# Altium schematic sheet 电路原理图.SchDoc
size 419 x 297 mm
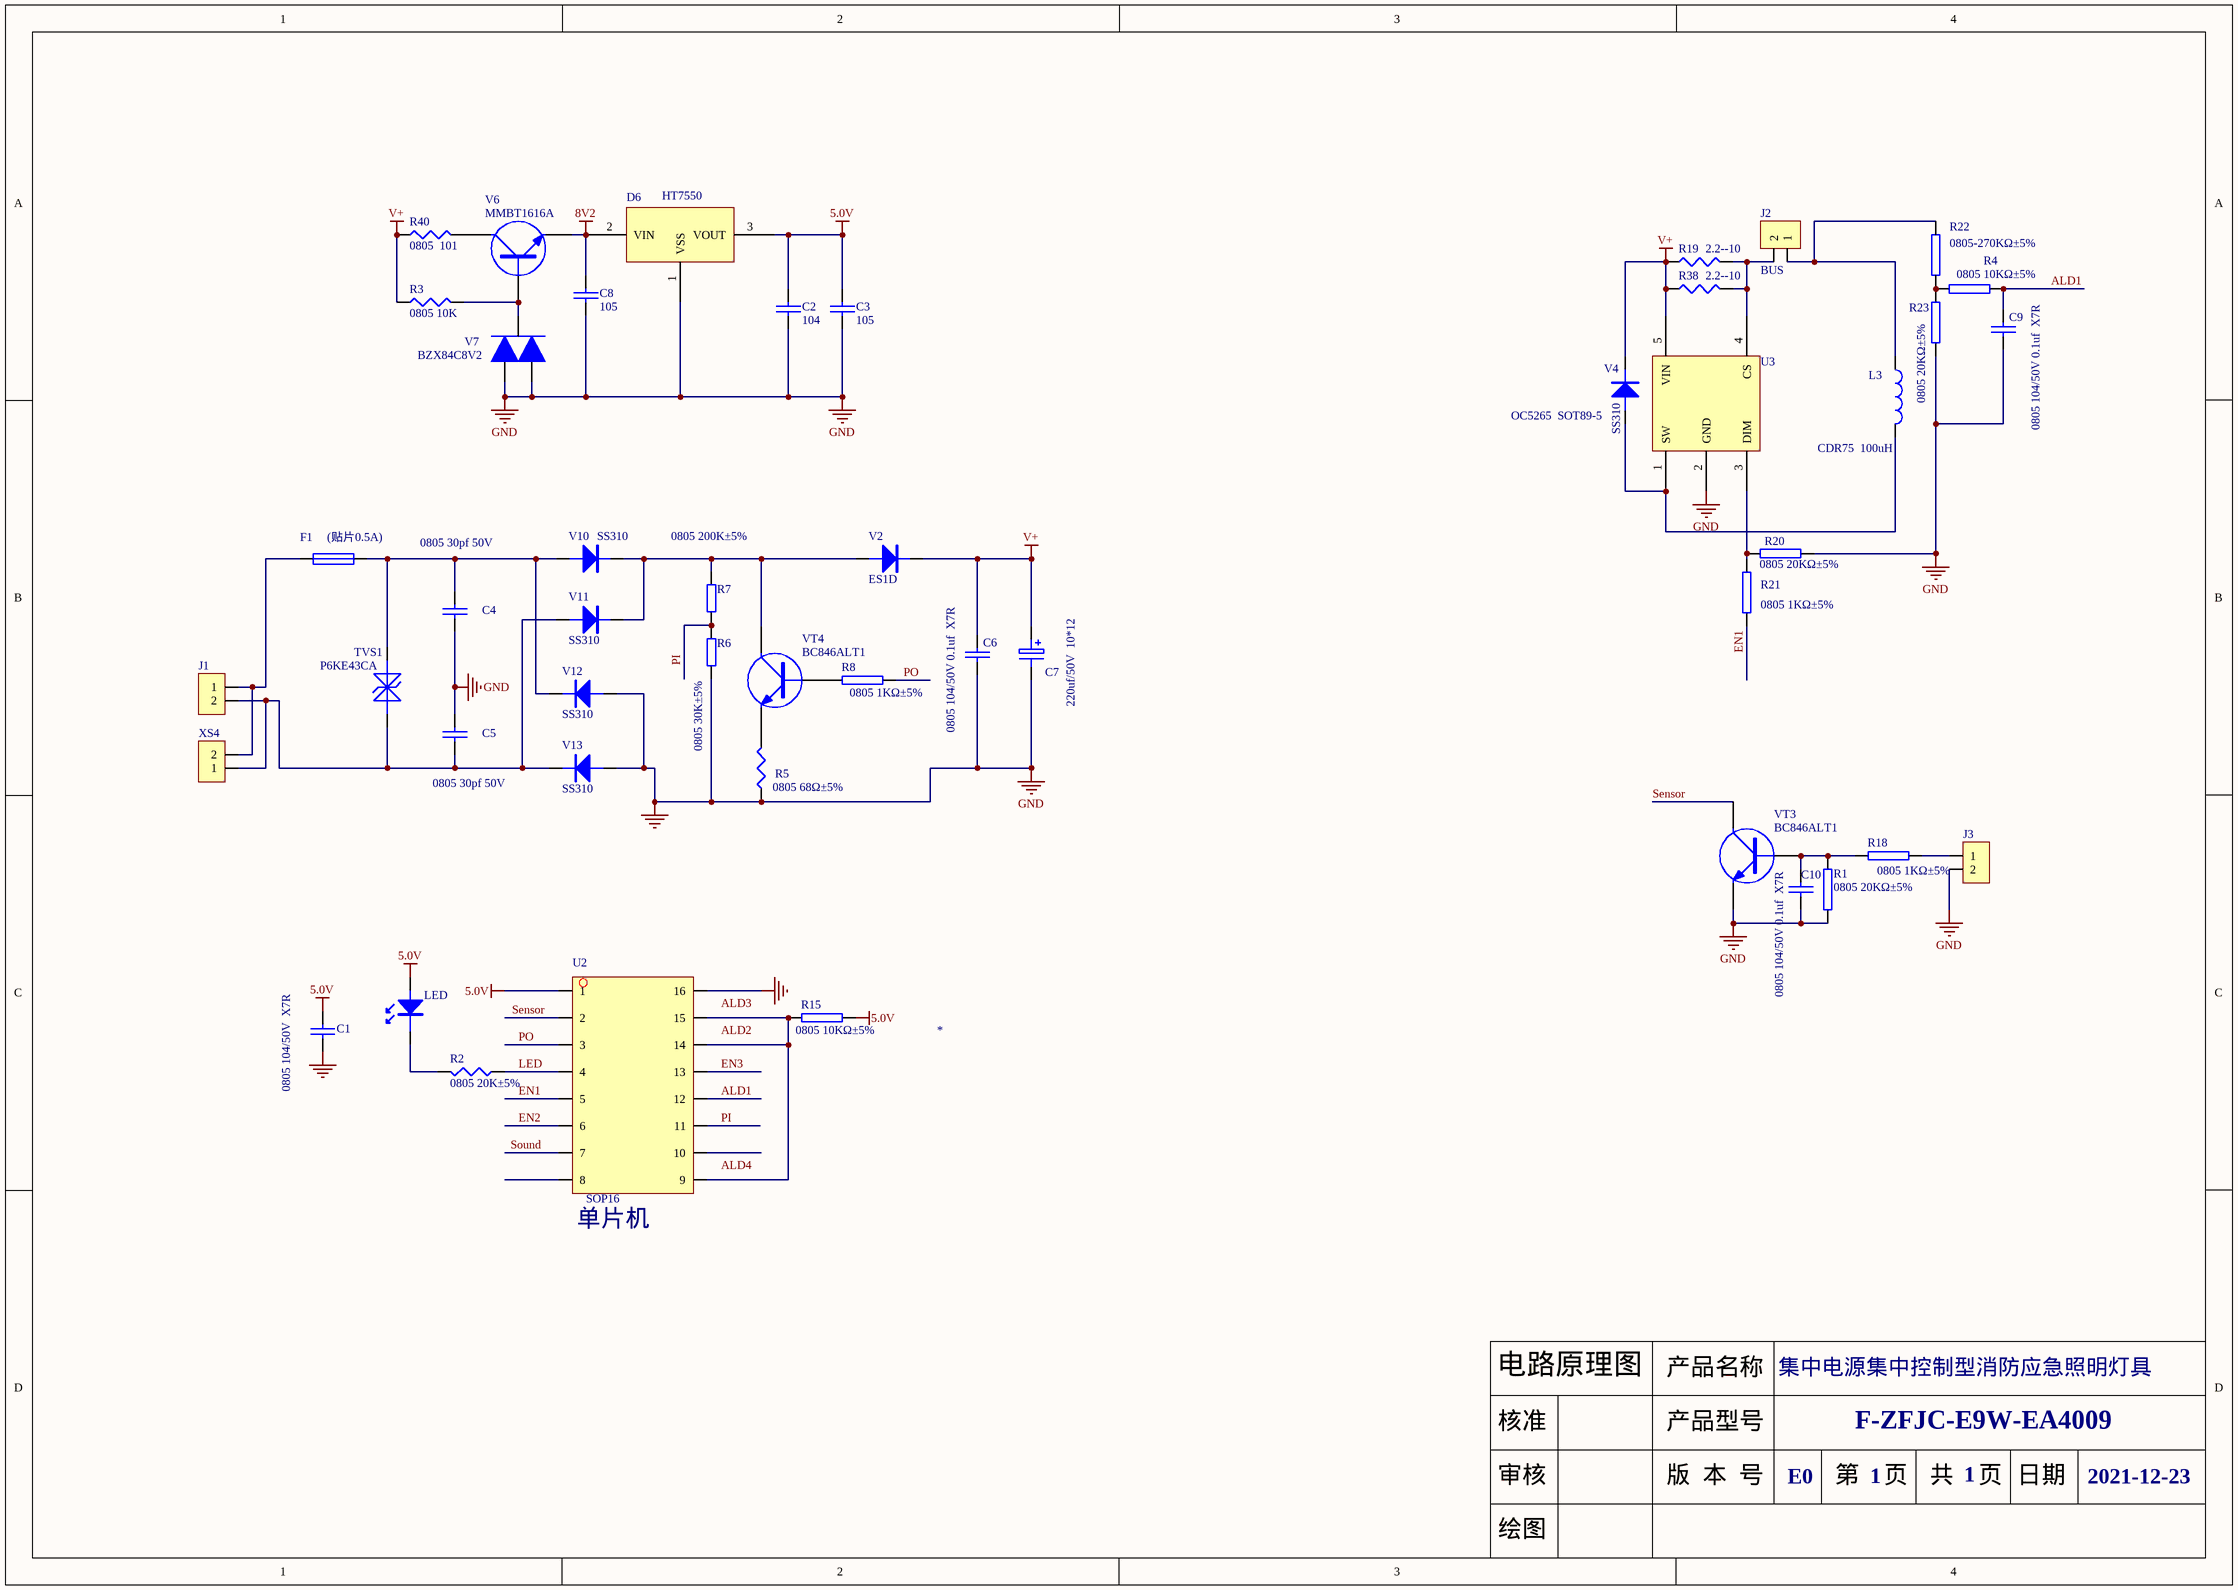
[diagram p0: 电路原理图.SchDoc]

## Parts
C1  0805 104/50V  X7R  [0805-C]
C2  104  [0805-c]
C3  105  [0805-C]
C4  0805 30pf 50V  [0805-c]
C5  0805 30pf 50V  [0805-c]
C6  0805 104/50V 0.1uf  X7R  [0805-c]
C7  220uf/50V  10*12  [CE10]
C8  105  [0805-C]
C9  0805 104/50V 0.1uf  X7R  [0805-c]
C10  0805 104/50V 0.1uf  X7R  [0805-c]
D6  HT7550  [SOT-89]
F1  (贴片0.5A)  [贴片保险]
J1  BUS  [SMT_J2]  (value not drawn)
J2  BUS  [贴片座子PCB封装]
J3  (no value)  [贴片座子PCB封装]
L3  CDR75  100uH  [L8]
LED  (no value)  [LED0805]
R1  0805 20KΩ±5%  [0805]
R2  0805 20K±5%  [0805]
R3  0805 10K  [1206]
R4  0805 10KΩ±5%  [0805]
R5  0805 68Ω±5%  [0805]
R6  0805 30K±5%  [0805]
R7  0805 200K±5%  [0805]
R8  0805 1KΩ±5%  [0805]
R15  0805 10KΩ±5%  [0805]
R18  0805 1KΩ±5%  [0805]
R19  2.2--10  [1206]
R20  0805 20KΩ±5%  [0805]
R21  0805 1KΩ±5%  [0805]
R22  0805-270KΩ±5%  [0805]
R23  0805 20KΩ±5%  [0805]
R38  2.2--10  [1206]
R40  0805  101  [0805]
TVS1  P6KE43CA  [SMT_TVS]
U2  SOP16  [SOP-16b]
U3  OC5265  SOT89-5  [SOT-89-5]
V2  ES1D  [SMA]
V4  SS310  [SMA]
V6  MMBT1616A  [SOT-23]
V7  BZX84C8V2  [SOT-23]
V10  SS310  [SMA]
V11  SS310  [SMA]
V12  SS310  [SMA]
V13  SS310  [SMA]
VT3  BC846ALT1  [SOT-23]
VT4  BC846ALT1  [SOT-23]
XS4  BUS  [TJC-2]  (value not drawn)

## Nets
5.0V: C1.2 C2.2 C3.2 D6.3(VOUT) LED.A R15.1 U2.1
8V2: C8.2 D6.2(VIN) V6.2(E)
GND: C1.1 C2.1 C3.1 C4.2 C5.1 C6.2 C7.2 C8.1 C9.2 C10.2 D6.1(VSS) J3.2 R1.2 R5.1 R6.1 R20.1 R23.1 U2.16 U3.2(GND) V7.1 V7.2 V12.A V13.A VT3.2(E)
V+: C6.1 C7.1 R3.1 R19.1 R38.1 R40.1 U3.5(VIN) V2.K V4.K
ALD1: C9.1 R4.1 U2.12
EN1: R21.1 U2.5
EN2: U2.6
EN3: U2.13
LED: R2.1 U2.4
PI: R6.2 R7.1 U2.11
PO: R8.2 U2.3
Sensor: U2.2 VT3.3(C)
Sound: U2.7
NetC4_1: C4.1 F1.2 TVS1.A V10.A V12.K
NetC5_2: C5.2 J1.2 TVS1.K V11.A V13.K XS4.1
NetC10_1: C10.1 R1.1 R18.1 VT3.1(B)
NetF1_1: F1.1 J1.1 XS4.2
NetJ2_1: J2.1 L3.1 R22.2
NetJ2_2: J2.2 R19.2 R38.2 U3.4(CS)
NetJ3_1: J3.1 R18.2
NetL3_2: L3.2 U3.1(SW) V4.A
NetLED_K: LED.K R2.2
NetR3_2: R3.2 V6.1(B) V7.3
NetR4_2: R4.2 R22.1 R23.2
NetR5_2: R5.2 VT4.2(E)
NetR7_2: R7.2 V2.A V10.K V11.K VT4.3(C)
NetR8_1: R8.1 VT4.1(B)
NetR15_2: R15.2 U2.9 U2.14 U2.15
NetR20_2: R20.2 R21.2 U3.3(DIM)
NetR40_2: R40.2 V6.3(C)

Not connected (* = marked no-connect by the designer): U2 8 10

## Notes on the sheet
- (near U2) 单片机
- 集中电源集中控制型消防应急照明灯具
- F-ZFJC-E9W-EA4009
- E0
- 1
- 2021-12-23
- Labels drawn without touching a wire or pin: ALD2, ALD3, ALD4

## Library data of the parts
C1 = CAP: 料号: 4.1.CTX.004; 型号规格: 104/50V ±10% X7R; 名称: 0603封装贴片电容
C2 C3 C8 = CAP
C4 C5 = CAP: 料号: 4.1.CTX.054; 型号规格: 30PF/50V ±10% X7R 5000H RoHS; 名称: 0603封装贴片电容
C6 C9 C10 = CAP: 料号: 4.1.CTX.004; 型号规格: 104/50V ±10% X7R 5000H RoHS; 名称: 0603封装贴片电容
C7 = ELECTRO1: 料号: 4.1.C.113; 型号规格: 330UF/50V 10*16 105℃ 误差±20% 5000-10000H 脚长(3.2-3.5mm); 名称: 电解电容
D6 = LDO
F1 = FUSE1: 料号: 4.3.X.111; 型号规格: 仓 24F系列 快断保险管 2A250V; 名称: 贴片保险管
J1 = CON2: 新料: 无
J2 = CON2: 型号规格: XH2.5-2A 白色直插针; 名称: 直插针座
J3 = CON2: 料号: 无; 型号规格: XH2.5-2A 白色直插针; 名称: 直插针座
L3 = INDUCTOR: 料号: 4.5.LG.151; 型号规格: CD54-100uH; 名称: 贴片电感
LED = LED: 料号: 4.3.LED.250; 名称: 发光二极管; 型号规格: C0805UG-ES 高亮白发绿贴片 VF:2.8-3.0 IV:250-300 WLD:515-520  IF:30MA
R1 R20 = RES2: 料号: 4.2.RTX.003; 型号规格: 103(10KΩ) ±5%; 名称: 0603封装贴片电阻
R2 = RES1: 料号: 4.2.RTD.246; 型号规格: 15R(15Ω) ±1%RoHS; 名称: 0805封装贴片电阻
R3 R40 = RES1
R4 R23 = RES2: 料号: 4.2.RTX.035A; 型号规格: 203(20KΩ) ±1%; 名称: 0603封装贴片电阻
R5 = RES1: 料号: 4.2.RTD.244; 型号规格: 680(68Ω) ±5%; 名称: 0805封装贴片电阻
R6 = RES: 料号: 4.2.RTD.044; 型号规格: 203(20KΩ) ±5%; 名称: 0805封装贴片电阻
R7 = RES: 料号: 4.2.RTD.130; 型号规格: 274(270KΩ) ±5%; 名称: 0805封装贴片电阻
R8 R15 R21 = RES2: 料号: 4.2.RTX.002; 型号规格: 102(1KΩ) ±5%; 名称: 0603封装贴片电阻
R18 = RES2: 料号: 无; 名称: 0603封装贴片电阻
R19 R38 = RES1: 料号: 调试待定; 名称: 1206贴片封装电阻
R22 = RES1: 料号: 4.2.RTX.009; 型号规格: 204(200KΩ) ±5%; 名称: 0603封装贴片电阻
TVS1 = TVS1: 料号: 4.3.DT.064; 型号规格: 瞬态二极管 P6KE43CA  SMT_TVS; 名称: 贴片瞬态二极管
U3 = BP1360: 料号: 新料; 名称: 贴片IC
V2 = DIODE: 料号: 4.3.D.033; 型号规格: ES1D 1A/200V SMA -55~125℃ RoHS，编带; 名称: 贴片超快恢复二极管
V4 V10-V13 = DIODE: 料号: 4.3.DT.065; 型号规格: SS310 SMA 3A/100V  RoHS; 名称: 贴片肖特基二极
V6 VT3 VT4 = NPN
V7 = BZX84C
XS4 = CON2: 型号规格: XH2.5-2A白色直插针座; 名称: 直插针座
